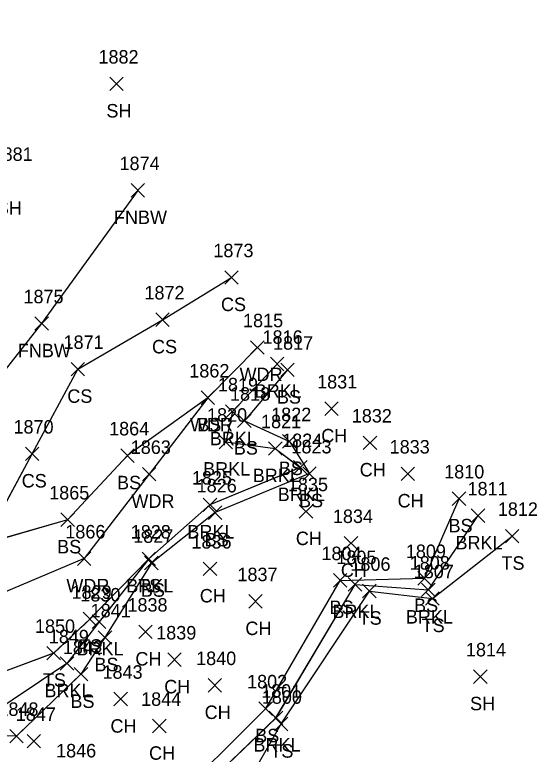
# Model space of a CAD drawing. Extents: x 1415642 to 1422021, y 544543 to 547232.
# Drawn here: x 1416204.6 to 1416280.8, y 546900.4 to 547010.1 of the extents above; entities that cross this region are included whole.
import ezdxf

# ---------------------------------------------------------------- set-up
doc = ezdxf.new("R2010")
doc.units = 0
for name, color, linetype in [('L_A', 7, 'Continuous'), ('L_I', 7, 'Continuous'), ('L_TIC', 7, 'Continuous'), ('LAWA', 7, 'Continuous'), ('LAWE', 7, 'Continuous'), ('LELB', 7, 'Continuous'), ('LFNC', 7, 'Continuous')]:
    doc.layers.add(name, color=color, linetype=linetype)

msp = doc.modelspace()

# ---------------------------------------------------------------- linework, layer by layer
at = {"layer": 'L_TIC'}
for points in [[(1416218.67, 546998.85), (1416220.67, 547000.85)], [(1416220.67, 546998.85), (1416218.67, 547000.85)], [(1416221.81, 546983.04), (1416223.81, 546985.04)], [(1416223.81, 546983.04), (1416221.81, 546985.04)], [(1416235.72, 546970.12), (1416237.72, 546972.12)], [(1416237.72, 546970.12), (1416235.72, 546972.12)], [(1416225.49, 546963.85), (1416227.49, 546965.85)], [(1416227.49, 546963.85), (1416225.49, 546965.85)], [(1416207.55, 546963.28), (1416209.55, 546965.28)], [(1416209.55, 546963.28), (1416207.55, 546965.28)], [(1416239.56, 546959.73), (1416241.56, 546961.73)], [(1416241.56, 546959.73), (1416239.56, 546961.73)], [(1416242.51, 546957.27), (1416244.51, 546959.27)], [(1416244.51, 546957.27), (1416242.51, 546959.27)], [(1416212.92, 546956.51), (1416214.92, 546958.51)], [(1416214.92, 546956.51), (1416212.92, 546958.51)], [(1416244.02, 546956.4), (1416246.02, 546958.4)], [(1416246.02, 546956.4), (1416244.02, 546958.4)], [(1416232.2, 546952.27), (1416234.2, 546954.27)], [(1416234.2, 546952.27), (1416232.2, 546954.27)], [(1416232.2, 546952.27), (1416234.2, 546954.27)], [(1416234.2, 546952.27), (1416232.2, 546954.27)], [(1416250.55, 546950.64), (1416252.55, 546952.64)], [(1416252.55, 546950.64), (1416250.55, 546952.64)], [(1416235.85, 546950.22), (1416237.85, 546952.22)], [(1416237.85, 546950.22), (1416235.85, 546952.22)], [(1416237.63, 546948.83), (1416239.63, 546950.83)], [(1416239.63, 546948.83), (1416237.63, 546950.83)], [(1416234.87, 546945.71), (1416236.87, 546947.71)], [(1416236.87, 546945.71), (1416234.87, 546947.71)], [(1416244.31, 546945.79), (1416246.31, 546947.79)], [(1416246.31, 546945.79), (1416244.31, 546947.79)], [(1416256.27, 546945.59), (1416258.27, 546947.59)], [(1416258.27, 546945.59), (1416256.27, 546947.59)], [(1416242.22, 546944.74), (1416244.22, 546946.74)], [(1416244.22, 546944.74), (1416242.22, 546946.74)], [(1416206.15, 546943.95), (1416208.15, 546945.95)], [(1416208.15, 546943.95), (1416206.15, 546945.95)], [(1416220.3, 546943.68), (1416222.3, 546945.68)], [(1416222.3, 546943.68), (1416220.3, 546945.68)], [(1416245.93, 546941.94), (1416247.93, 546943.94)], [(1416247.93, 546941.94), (1416245.93, 546943.94)], [(1416223.51, 546940.93), (1416225.51, 546942.93)], [(1416225.51, 546940.93), (1416223.51, 546942.93)], [(1416247.3, 546941.01), (1416249.3, 546943.01)], [(1416249.3, 546941.01), (1416247.3, 546943.01)], [(1416261.88, 546940.99), (1416263.88, 546942.99)], [(1416263.88, 546940.99), (1416261.88, 546942.99)], [(1416232.53, 546936.38), (1416234.53, 546938.38)], [(1416234.53, 546936.38), (1416232.53, 546938.38)], [(1416269.49, 546937.29), (1416271.49, 546939.29)], [(1416271.49, 546937.29), (1416269.49, 546939.29)], [(1416233.3, 546935.22), (1416235.3, 546937.22)], [(1416235.3, 546935.22), (1416233.3, 546937.22)], [(1416246.78, 546935.4), (1416248.78, 546937.4)], [(1416248.78, 546935.4), (1416246.78, 546937.4)], [(1416211.41, 546934.17), (1416213.41, 546936.17)], [(1416213.41, 546934.17), (1416211.41, 546936.17)], [(1416272.31, 546934.77), (1416274.31, 546936.77)], [(1416274.31, 546934.77), (1416272.31, 546936.77)], [(1416277.37, 546931.74), (1416279.37, 546933.74)], [(1416279.37, 546931.74), (1416277.37, 546933.74)], [(1416253.46, 546930.68), (1416255.46, 546932.68)], [(1416255.46, 546930.68), (1416253.46, 546932.68)], [(1416213.85, 546928.39), (1416215.85, 546930.39)], [(1416215.85, 546928.39), (1416213.85, 546930.39)], [(1416223.46, 546928.37), (1416225.46, 546930.37)], [(1416225.46, 546928.37), (1416223.46, 546930.37)], [(1416223.46, 546928.37), (1416225.46, 546930.37)], [(1416225.46, 546928.37), (1416223.46, 546930.37)], [(1416223.83, 546927.74), (1416225.83, 546929.74)], [(1416225.83, 546927.74), (1416223.83, 546929.74)], [(1416232.53, 546926.89), (1416234.53, 546928.89)], [(1416234.53, 546926.89), (1416232.53, 546928.89)], [(1416264.37, 546925.48), (1416266.37, 546927.48)], [(1416266.37, 546925.48), (1416264.37, 546927.48)], [(1416251.84, 546925.17), (1416253.84, 546927.17)], [(1416253.84, 546925.17), (1416251.84, 546927.17)], [(1416254.05, 546924.58), (1416256.05, 546926.58)], [(1416256.05, 546924.58), (1416254.05, 546926.58)], [(1416256.18, 546923.59), (1416258.18, 546925.59)], [(1416258.18, 546923.59), (1416256.18, 546925.59)], [(1416264.94, 546923.76), (1416266.94, 546925.76)], [(1416266.94, 546923.76), (1416264.94, 546925.76)], [(1416239.29, 546922.05), (1416241.29, 546924.05)], [(1416241.29, 546922.05), (1416239.29, 546924.05)], [(1416265.53, 546922.49), (1416267.53, 546924.49)], [(1416267.53, 546922.49), (1416265.53, 546924.49)], [(1416214.69, 546919.43), (1416216.69, 546921.43)], [(1416216.69, 546919.43), (1416214.69, 546921.43)], [(1416216.07, 546919.04), (1416218.07, 546921.04)], [(1416218.07, 546919.04), (1416216.07, 546921.04)], [(1416216.95, 546916.68), (1416218.95, 546918.68)], [(1416218.95, 546916.68), (1416216.95, 546918.68)], [(1416222.97, 546917.53), (1416224.97, 546919.53)], [(1416224.97, 546917.53), (1416222.97, 546919.53)], [(1416209.33, 546914.38), (1416211.33, 546916.38)], [(1416211.33, 546914.38), (1416209.33, 546916.38)], [(1416227.25, 546913.4), (1416229.25, 546915.4)], [(1416229.25, 546913.4), (1416227.25, 546915.4)], [(1416211.31, 546912.83), (1416213.31, 546914.83)], [(1416213.31, 546912.83), (1416211.31, 546914.83)], [(1416213.38, 546911.24), (1416215.38, 546913.24)], [(1416215.38, 546911.24), (1416213.38, 546913.24)], [(1416272.64, 546910.89), (1416274.64, 546912.89)], [(1416274.64, 546910.89), (1416272.64, 546912.89)], [(1416233.25, 546909.6), (1416235.25, 546911.6)], [(1416235.25, 546909.6), (1416233.25, 546911.6)], [(1416219.27, 546907.57), (1416221.27, 546909.57)], [(1416221.27, 546907.57), (1416219.27, 546909.57)], [(1416240.8, 546906.14), (1416242.8, 546908.14)], [(1416242.8, 546906.14), (1416240.8, 546908.14)], [(1416242.32, 546904.76), (1416244.32, 546906.76)], [(1416244.32, 546904.76), (1416242.32, 546906.76)], [(1416225.01, 546903.55), (1416227.01, 546905.55)], [(1416227.01, 546903.55), (1416225.01, 546905.55)], [(1416243.08, 546903.86), (1416245.08, 546905.86)], [(1416245.08, 546903.86), (1416243.08, 546905.86)], [(1416203.83, 546902.06), (1416205.83, 546904.06)], [(1416205.83, 546902.06), (1416203.83, 546904.06)], [(1416206.4, 546901.32), (1416208.4, 546903.32)], [(1416208.4, 546901.32), (1416206.4, 546903.32)]]:
    msp.add_lwpolyline(points, dxfattribs=at)
at = {"layer": 'LAWA'}
for points in [[(1416240.56, 546960.73), (1416233.2, 546953.27), (1416224.51, 546941.93), (1416214.85, 546929.39), (1416199.95, 546923.14), (1416193.46, 546920.24), (1416179.13, 546920.7), (1416159.93, 546927.15), (1416126.32, 546945.38), (1416100.02, 546952.8), (1416028.43, 546991.66), (1415993.05, 547010.51), (1415954.88, 547028.97)], [(1416240.56, 546960.73), (1416233.2, 546953.27), (1416224.51, 546941.93), (1416214.86, 546929.39), (1416199.95, 546923.14), (1416193.46, 546920.24), (1416179.13, 546920.7), (1416159.93, 546927.15), (1416126.32, 546945.39), (1416100.02, 546952.81), (1416028.43, 546991.66), (1415993.05, 547010.51), (1415954.88, 547028.96)]]:
    msp.add_lwpolyline(points, dxfattribs=at)
at = {"layer": 'LAWE'}
for points in [[(1416243.51, 546958.27), (1416236.85, 546951.22), (1416235.87, 546946.71), (1416243.22, 546945.74), (1416246.93, 546942.94), (1416233.53, 546937.38), (1416224.46, 546929.37), (1416217.07, 546920.04), (1416212.31, 546913.83), (1416200.05, 546905.66)], [(1416243.51, 546958.26), (1416236.85, 546951.23), (1416235.87, 546946.71), (1416243.22, 546945.74), (1416246.94, 546942.94), (1416233.53, 546937.38), (1416224.46, 546929.36), (1416217.07, 546920.04), (1416212.31, 546913.83), (1416200.05, 546905.66)], [(1416230.16, 546893.12), (1416243.32, 546905.76), (1416255.05, 546925.58), (1416265.94, 546924.76), (1416273.31, 546935.77)], [(1416230.16, 546893.12), (1416243.33, 546905.76), (1416255.05, 546925.58), (1416265.95, 546924.76), (1416273.31, 546935.77)]]:
    msp.add_lwpolyline(points, dxfattribs=at)
at = {"layer": 'LELB'}
for points in [[(1416199.92, 546931.56), (1416207.15, 546944.95), (1416213.92, 546957.51), (1416226.49, 546964.85), (1416236.72, 546971.12)], [(1416199.92, 546931.57), (1416207.15, 546944.94), (1416213.92, 546957.51), (1416226.49, 546964.85), (1416236.72, 546971.12)], [(1416245.02, 546957.4), (1416238.63, 546949.83), (1416245.31, 546946.79), (1416248.3, 546942.01), (1416234.3, 546936.22), (1416224.83, 546928.74), (1416217.95, 546917.68), (1416214.38, 546912.24), (1416204.83, 546903.06), (1416200.09, 546903.2)], [(1416245.02, 546957.4), (1416238.63, 546949.83), (1416245.31, 546946.79), (1416248.31, 546942.01), (1416234.3, 546936.22), (1416224.83, 546928.74), (1416217.94, 546917.68), (1416214.38, 546912.24), (1416204.83, 546903.06), (1416200.1, 546903.2)], [(1416233.2, 546953.27), (1416221.3, 546944.68), (1416212.41, 546935.17), (1416199.92, 546931.56), (1416185.45, 546936.31)], [(1416233.2, 546953.27), (1416221.3, 546944.68), (1416212.41, 546935.17), (1416199.92, 546931.57), (1416185.45, 546936.31)], [(1416227.02, 546892.43), (1416241.8, 546907.14), (1416252.84, 546926.17), (1416265.37, 546926.48), (1416270.49, 546938.29)], [(1416227.02, 546892.43), (1416241.8, 546907.14), (1416252.84, 546926.17), (1416265.36, 546926.48), (1416270.49, 546938.28)], [(1416238.66, 546895.34), (1416244.08, 546904.86), (1416257.18, 546924.59), (1416266.53, 546923.49), (1416278.37, 546932.74)], [(1416238.67, 546895.34), (1416244.08, 546904.86), (1416257.19, 546924.59), (1416266.53, 546923.49), (1416278.37, 546932.74)], [(1416224.46, 546929.37), (1416215.69, 546920.43), (1416210.33, 546915.38), (1416200.86, 546911.84), (1416197.14, 546917.85)], [(1416224.46, 546929.36), (1416215.7, 546920.43), (1416210.34, 546915.38), (1416200.86, 546911.84), (1416197.14, 546917.85)]]:
    msp.add_lwpolyline(points, dxfattribs=at)
at = {"layer": 'LFNC'}
for points in [[(1416222.81, 546984.04), (1416208.55, 546964.28), (1416198.91, 546952.13), (1416189.48, 546940.48), (1416185.45, 546936.31), (1416182.76, 546933.14), (1416166.21, 546941.06), (1416137.35, 546954.69), (1416104.96, 546968.84)], [(1416222.81, 546984.03), (1416208.55, 546964.28), (1416198.92, 546952.14), (1416189.48, 546940.48), (1416185.45, 546936.31), (1416182.77, 546933.14), (1416166.21, 546941.06), (1416137.36, 546954.69), (1416104.96, 546968.84)]]:
    msp.add_lwpolyline(points, dxfattribs=at)

# ---------------------------------------------------------------- texts
at = {"layer": 'L_A'}
for s, p in [('SH', (1416218.16, 546994.85)), ('SH', (1416201.89, 546980.41)), ('FNBW', (1416219.28, 546979.04)), ('CS', (1416235.16, 546966.12)), ('CS', (1416224.93, 546959.85)), ('FNBW', (1416205.02, 546959.28)), ('WDR', (1416237.92, 546955.73)), ('BRKL', (1416240.16, 546953.27)), ('CS', (1416212.36, 546952.51)), ('BS', (1416243.46, 546952.4)), ('WDR', (1416230.56, 546948.27)), ('BS', (1416231.64, 546948.27)), ('BRKL', (1416233.49, 546946.22)), ('CH', (1416250.04, 546946.64)), ('BS', (1416237.07, 546944.83)), ('BS', (1416243.75, 546941.79)), ('BRKL', (1416232.51, 546941.71)), ('BRKL', (1416239.87, 546940.74)), ('CH', (1416255.75, 546941.59)), ('CS', (1416205.59, 546939.95)), ('BS', (1416219.74, 546939.68)), ('BRKL', (1416243.58, 546937.94)), ('WDR', (1416221.87, 546936.93)), ('BS', (1416246.74, 546937.01)), ('CH', (1416261.37, 546936.99)), ('BS', (1416268.93, 546933.29)), ('BRKL', (1416230.17, 546932.38)), ('BS', (1416232.74, 546931.22)), ('CH', (1416246.27, 546931.4)), ('BS', (1416210.85, 546930.17)), ('BRKL', (1416269.96, 546930.77)), ('TS', (1416276.78, 546927.74)), ('CH', (1416252.95, 546926.68)), ('WDR', (1416212.22, 546924.39)), ('BRKL', (1416221.11, 546924.37)), ('TS', (1416222.87, 546924.37)), ('BS', (1416223.27, 546923.74)), ('CH', (1416232.02, 546922.89)), ('BS', (1416251.28, 546921.17)), ('BS', (1416263.81, 546921.48)), ('BRKL', (1416251.69, 546920.58)), ('TS', (1416255.59, 546919.59)), ('BRKL', (1416262.59, 546919.76)), ('CH', (1416238.78, 546918.05)), ('TS', (1416264.94, 546918.49)), ('TS', (1416214.1, 546915.43)), ('BRKL', (1416213.71, 546915.04)), ('CH', (1416222.46, 546913.53)), ('BS', (1416216.39, 546912.68)), ('TS', (1416208.74, 546910.38)), ('CH', (1416226.74, 546909.4)), ('BRKL', (1416208.96, 546908.83)), ('BS', (1416212.82, 546907.24)), ('SH', (1416272.12, 546906.89)), ('CH', (1416232.74, 546905.6)), ('CH', (1416218.76, 546903.57)), ('BS', (1416240.24, 546902.14)), ('BRKL', (1416239.97, 546900.76)), ('CH', (1416224.49, 546899.55)), ('TS', (1416242.49, 546899.86))]:
    msp.add_text(s, height=2, dxfattribs=at).set_placement(p)
at = {"layer": 'L_I'}
for s, p in [('1882', (1416216.98, 547002.85)), ('1881', (1416201.27, 546988.41)), ('1874', (1416220.11, 546987.04)), ('1873', (1416234.03, 546974.12)), ('1875', (1416205.85, 546967.28)), ('1872', (1416223.8, 546967.85)), ('1815', (1416238.43, 546963.73)), ('1871', (1416211.8, 546960.51)), ('1816', (1416241.33, 546961.27)), ('1817', (1416242.89, 546960.4)), ('1862', (1416230.46, 546956.27)), ('1862', (1416230.46, 546956.27)), ('1819', (1416234.71, 546954.22)), ('1831', (1416249.43, 546954.64)), ('1818', (1416236.5, 546952.83)), ('1820', (1416233.09, 546949.71)), ('1822', (1416242.61, 546949.79)), ('1832', (1416254.57, 546949.59)), ('1821', (1416241.1, 546948.74)), ('1870', (1416204.37, 546947.95)), ('1864', (1416218.56, 546947.68)), ('1824', (1416244.24, 546945.94)), ('1863', (1416221.77, 546944.93)), ('1823', (1416245.61, 546945.01)), ('1833', (1416260.19, 546944.99)), ('1810', (1416268.28, 546941.29)), ('1825', (1416230.84, 546940.38)), ('1826', (1416231.55, 546939.22)), ('1835', (1416245.09, 546939.4)), ('1811', (1416271.75, 546938.77)), ('1865', (1416209.67, 546938.17)), ('1812', (1416276.24, 546935.74)), ('1834', (1416251.77, 546934.68)), ('1866', (1416212.06, 546932.39)), ('1828', (1416221.77, 546932.37)), ('1828', (1416221.77, 546932.37)), ('1827', (1416222.14, 546931.74)), ('1836', (1416230.78, 546930.89)), ('1804', (1416250.07, 546929.17)), ('1805', (1416252.28, 546928.58)), ('1809', (1416262.59, 546929.48)), ('1806', (1416254.36, 546927.59)), ('1808', (1416263.17, 546927.76)), ('1807', (1416263.76, 546926.49)), ('1837', (1416237.6, 546926.05)), ('1829', (1416212.99, 546923.43)), ('1830', (1416214.29, 546923.04)), ('1838', (1416221.28, 546921.53)), ('1841', (1416215.82, 546920.68)), ('1850', (1416207.56, 546918.38)), ('1849', (1416209.61, 546916.83)), ('1839', (1416225.55, 546917.4)), ('1842', (1416211.69, 546915.24)), ('1814', (1416271.51, 546914.89)), ('1840', (1416231.47, 546913.6)), ('1843', (1416217.58, 546911.57)), ('1802', (1416239.03, 546910.14)), ('1801', (1416241.12, 546908.76)), ('1800', (1416241.22, 546907.86)), ('1844', (1416223.31, 546907.55)), ('1848', (1416202.13, 546906.06)), ('1847', (1416204.71, 546905.32)), ('1846', (1416210.69, 546899.9))]:
    msp.add_text(s, height=2, dxfattribs=at).set_placement(p)

doc.saveas('drawing.dxf')
